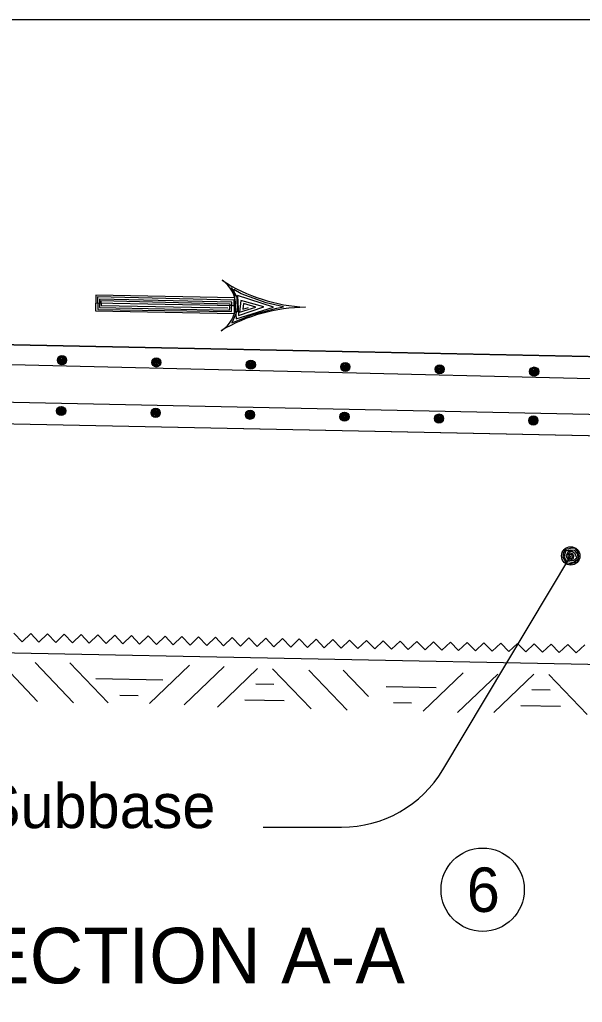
# Model space of a CAD drawing. Extents: x 10130 to 81668, y 5440 to 21644.
# Drawn here: x 17774.7 to 17977.5, y 9590.3 to 9944 of the extents above; entities that cross this region are included whole.
import ezdxf

# ---------------------------------------------------------------- set-up
doc = ezdxf.new("R2010")
doc.units = 0
for name, color, linetype in [('dsnStdBlockModified', 7, 'Continuous'), ('dsnStdBlockNotModified', 7, 'Continuous'), ('dsnStdBorder', 7, 'Continuous'), ('Level 2', 7, 'Continuous'), ('SheetBorder', 7, 'Continuous')]:
    doc.layers.add(name, color=color, linetype=linetype)

msp = doc.modelspace()

# ---------------------------------------------------------------- linework, layer by layer
at = {"layer": 'dsnStdBlockModified'}
msp.add_line((18198.1, 9797.36), (17466.58, 9812.52), dxfattribs=at)
at = {"layer": 'dsnStdBlockNotModified'}
for p, q in [((17852.17, 9844.06), (17852.17, 9844.06)), ((17852.26, 9841.03), (17802.12, 9842.03)), ((17852.11, 9838.2), (17852.11, 9838.2)), ((17927.27, 9674.05), (17973.29, 9751.03)), ((17862.47, 9653.35), (17890.76, 9653.35))]:
    msp.add_line(p, q, dxfattribs=at)
for points in [[(17850.94, 9847.58), (17853, 9844.16), (17853.16, 9839.21), (17851.25, 9834.92), (17858.71, 9837.84), (17867.4, 9840.18), (17869.85, 9840.69), (17863.61, 9842.07), (17854.6, 9845.38), (17851.93, 9846.88), (17852.72, 9836.34), (17866.15, 9840.58), (17853.2, 9844.78), (17853.56, 9837.51), (17862.77, 9840.71), (17854.42, 9842.94), (17853.96, 9838.76), (17859.83, 9840.51), (17855.4, 9841.86), (17855.11, 9839.86), (17857.25, 9840.44)], [(17852.22, 9843.87), (17802.18, 9844.87), (17802.06, 9839.2), (17852.11, 9838.2), (17852.04, 9843.05), (17802.81, 9844.23), (17802.85, 9839.72), (17851.02, 9838.94), (17851.21, 9842.32), (17803.49, 9843.46), (17803.55, 9840.45), (17850.4, 9839.51), (17850.57, 9841.64), (17804.04, 9842.83), (17804.07, 9841.13), (17849.79, 9840.28)], [(17973.03, 9747.99), (17974.15, 9748.49), (17975.88, 9749.03), (17976.22, 9750.79), (17975.98, 9752.34), (17974.87, 9753.77), (17973.22, 9753.62), (17971.47, 9753.37), (17970.64, 9751.99), (17970.49, 9750.52), (17971.52, 9748.61), (17972.79, 9748.45), (17974.53, 9748.89), (17975.95, 9750), (17975.9, 9751.65), (17974.79, 9752.98), (17973.23, 9753.13), (17971.49, 9752.79), (17971.23, 9751.81), (17970.88, 9750.63), (17971.69, 9749.19), (17972.96, 9749.23), (17974.41, 9749.47), (17975.46, 9750.28), (17974.93, 9751.72), (17973.83, 9752.57), (17972.37, 9752.62), (17972, 9751.83), (17971.54, 9750.94), (17972.26, 9749.8), (17973.34, 9749.54), (17974.3, 9750.05), (17974.37, 9751.12), (17973.86, 9751.88), (17972.87, 9752.15), (17972.4, 9751.75), (17972.12, 9751.15), (17972.64, 9750.29), (17973.32, 9750.12), (17973.99, 9750.53), (17973.88, 9751.11), (17973.38, 9751.48), (17972.7, 9751.47), (17972.71, 9750.98), (17973.3, 9750.7)]]:
    msp.add_lwpolyline(points, dxfattribs=at)
msp.add_circle((17973.29, 9751.02), 3.31, dxfattribs=at)
for centre, radius, start, end in [((17841.88, 9841.24), 10.67, 300.5647, 57.1354), ((17880.75, 9901.39), 60.95, 237.1358, 267.1658), ((17878.3, 9779.57), 60.95, 90.5343, 120.5643), ((17890.76, 9695.89), 42.54, 270, 329.1249)]:
    msp.add_arc(centre, radius, start, end, dxfattribs=at)
at = {"layer": 'dsnStdBorder'}
for p, q in [((18176.88, 9818.81), (17466.62, 9833.07)), ((17466.62, 9833.07), (18176.88, 9818.81)), ((17466.59, 9827.31), (18198.18, 9809.65)), ((17466.05, 9804.71), (18215.16, 9789.67)), ((17467.19, 9804.69), (18215.16, 9789.67)), ((17466.62, 9722.28), (18283.21, 9705.89)), ((17767.3, 9713.07), (17781.16, 9698.65)), ((17780.31, 9712.59), (17794.16, 9698.16)), ((17792.76, 9712.56), (17806.61, 9698.14)), ((17835.97, 9711.7), (17821.55, 9697.84)), ((17848.42, 9711.22), (17833.99, 9697.37)), ((17860.46, 9710.46), (17846.04, 9696.61)), ((17865.87, 9710.36), (17879.73, 9695.93)), ((17878.88, 9709.87), (17892.73, 9695.45)), ((17891.33, 9709.84), (17900.43, 9700.37)), ((17934.54, 9708.98), (17920.12, 9695.12)), ((17946.99, 9708.5), (17932.56, 9694.65)), ((17960, 9708.47), (17945.57, 9694.61)), ((17965.41, 9708.36), (17979.26, 9693.93))]:
    msp.add_line(p, q, dxfattribs=at)
for points in [[(17788.47, 9821.41), (17788.74, 9821.96), (17789.04, 9822.81), (17789.93, 9822.94), (17790.7, 9822.79), (17791.39, 9822.2), (17791.28, 9821.38), (17791.12, 9820.51), (17790.41, 9820.13), (17789.67, 9820.08), (17788.74, 9820.64), (17788.69, 9821.27), (17788.95, 9822.14), (17789.53, 9822.83), (17790.36, 9822.76), (17791, 9822.18), (17791.04, 9821.4), (17790.83, 9820.54), (17790.34, 9820.42), (17789.74, 9820.27), (17789.04, 9820.71), (17789.08, 9821.35), (17789.23, 9822.07), (17789.66, 9822.57), (17790.37, 9822.28), (17790.77, 9821.71), (17790.76, 9820.98), (17790.36, 9820.81), (17789.91, 9820.6), (17789.35, 9820.98), (17789.24, 9821.53), (17789.52, 9822), (17790.06, 9822.01), (17790.43, 9821.74), (17790.54, 9821.24), (17790.33, 9821.01), (17790.03, 9820.89), (17789.6, 9821.16), (17789.54, 9821.51), (17789.75, 9821.83), (17790.04, 9821.76), (17790.22, 9821.51), (17790.19, 9821.17), (17789.95, 9821.18), (17789.83, 9821.49)], [(17822.49, 9820.59), (17822.77, 9821.14), (17823.07, 9821.99), (17823.96, 9822.12), (17824.73, 9821.97), (17825.42, 9821.38), (17825.31, 9820.56), (17825.15, 9819.69), (17824.44, 9819.3), (17823.7, 9819.26), (17822.77, 9819.82), (17822.72, 9820.46), (17822.98, 9821.31), (17823.56, 9822.01), (17824.39, 9821.94), (17825.03, 9821.36), (17825.07, 9820.58), (17824.86, 9819.71), (17824.37, 9819.6), (17823.77, 9819.45), (17823.07, 9819.9), (17823.11, 9820.52), (17823.26, 9821.25), (17823.69, 9821.75), (17824.4, 9821.45), (17824.8, 9820.89), (17824.79, 9820.16), (17824.39, 9819.99), (17823.94, 9819.78), (17823.38, 9820.17), (17823.27, 9820.71), (17823.55, 9821.18), (17824.09, 9821.19), (17824.46, 9820.92), (17824.57, 9820.42), (17824.35, 9820.19), (17824.06, 9820.07), (17823.64, 9820.34), (17823.56, 9820.69), (17823.78, 9821.01), (17824.07, 9820.94), (17824.25, 9820.69), (17824.22, 9820.35), (17823.98, 9820.36), (17823.85, 9820.67)], [(17856.52, 9819.77), (17856.79, 9820.31), (17857.1, 9821.17), (17857.99, 9821.3), (17858.76, 9821.14), (17859.45, 9820.56), (17859.34, 9819.74), (17859.18, 9818.87), (17858.47, 9818.49), (17857.73, 9818.44), (17856.8, 9818.99), (17856.75, 9819.63), (17857, 9820.5), (17857.59, 9821.18), (17858.42, 9821.12), (17859.06, 9820.54), (17859.1, 9819.75), (17858.89, 9818.89), (17858.39, 9818.78), (17857.8, 9818.63), (17857.1, 9819.07), (17857.14, 9819.71), (17857.29, 9820.42), (17857.72, 9820.93), (17858.43, 9820.64), (17858.82, 9820.07), (17858.82, 9819.34), (17858.42, 9819.17), (17857.97, 9818.96), (17857.41, 9819.34), (17857.3, 9819.89), (17857.58, 9820.36), (17858.12, 9820.36), (17858.49, 9820.09), (17858.6, 9819.6), (17858.39, 9819.37), (17858.09, 9819.24), (17857.66, 9819.52), (17857.59, 9819.86), (17857.81, 9820.19), (17858.1, 9820.12), (17858.28, 9819.86), (17858.25, 9819.53), (17858.01, 9819.54), (17857.88, 9819.84)], [(17890.55, 9818.94), (17890.83, 9819.49), (17891.13, 9820.35), (17892.02, 9820.48), (17892.79, 9820.33), (17893.48, 9819.74), (17893.37, 9818.92), (17893.21, 9818.05), (17892.5, 9817.66), (17891.76, 9817.62), (17890.83, 9818.18), (17890.78, 9818.82), (17891.03, 9819.67), (17891.63, 9820.36), (17892.44, 9820.3), (17893.09, 9819.71), (17893.12, 9818.94), (17892.92, 9818.07), (17892.42, 9817.96), (17891.83, 9817.81), (17891.13, 9818.25), (17891.17, 9818.88), (17891.32, 9819.61), (17891.75, 9820.11), (17892.46, 9819.81), (17892.85, 9819.25), (17892.85, 9818.51), (17892.45, 9818.35), (17892, 9818.14), (17891.44, 9818.52), (17891.33, 9819.07), (17891.61, 9819.53), (17892.15, 9819.54), (17892.52, 9819.27), (17892.63, 9818.78), (17892.42, 9818.55), (17892.12, 9818.42), (17891.69, 9818.7), (17891.62, 9819.05), (17891.84, 9819.37), (17892.13, 9819.3), (17892.31, 9819.05), (17892.28, 9818.7), (17892.04, 9818.72), (17891.91, 9819.02)], [(17924.58, 9818.12), (17924.86, 9818.67), (17925.16, 9819.53), (17926.05, 9819.66), (17926.82, 9819.5), (17927.51, 9818.92), (17927.4, 9818.09), (17927.24, 9817.23), (17926.53, 9816.84), (17925.79, 9816.8), (17924.86, 9817.35), (17924.81, 9817.99), (17925.06, 9818.85), (17925.65, 9819.54), (17926.47, 9819.48), (17927.11, 9818.9), (17927.15, 9818.11), (17926.95, 9817.25), (17926.45, 9817.14), (17925.86, 9816.99), (17925.16, 9817.43), (17925.2, 9818.06), (17925.35, 9818.78), (17925.78, 9819.29), (17926.49, 9818.99), (17926.89, 9818.43), (17926.88, 9817.69), (17926.48, 9817.53), (17926.03, 9817.32), (17925.47, 9817.7), (17925.36, 9818.24), (17925.64, 9818.71), (17926.18, 9818.72), (17926.55, 9818.45), (17926.66, 9817.95), (17926.44, 9817.72), (17926.14, 9817.6), (17925.72, 9817.88), (17925.66, 9818.22), (17925.87, 9818.55), (17926.16, 9818.48), (17926.34, 9818.22), (17926.31, 9817.88), (17926.07, 9817.9), (17925.95, 9818.2)], [(17958.61, 9817.3), (17958.88, 9817.85), (17959.19, 9818.71), (17960.08, 9818.84), (17960.85, 9818.68), (17961.54, 9818.09), (17961.43, 9817.28), (17961.26, 9816.41), (17960.55, 9816.02), (17959.82, 9815.98), (17958.88, 9816.53), (17958.84, 9817.17), (17959.09, 9818.03), (17959.68, 9818.72), (17960.5, 9818.66), (17961.14, 9818.07), (17961.18, 9817.29), (17960.98, 9816.43), (17960.48, 9816.32), (17959.89, 9816.17), (17959.19, 9816.61), (17959.23, 9817.24), (17959.38, 9817.96), (17959.81, 9818.47), (17960.52, 9818.17), (17960.91, 9817.61), (17960.91, 9816.87), (17960.51, 9816.71), (17960.06, 9816.5), (17959.5, 9816.88), (17959.39, 9817.43), (17959.67, 9817.89), (17960.21, 9817.9), (17960.58, 9817.63), (17960.69, 9817.13), (17960.48, 9816.91), (17960.17, 9816.78), (17959.75, 9817.05), (17959.68, 9817.4), (17959.9, 9817.73), (17960.19, 9817.66), (17960.37, 9817.4), (17960.34, 9817.06), (17960.1, 9817.08), (17959.97, 9817.38)], [(17791.2, 9803.05), (17790.95, 9803.61), (17790.69, 9804.48), (17789.8, 9804.64), (17789.03, 9804.52), (17788.31, 9803.97), (17788.39, 9803.14), (17788.51, 9802.27), (17789.2, 9801.85), (17789.94, 9801.77), (17790.9, 9802.29), (17790.97, 9802.92), (17790.76, 9803.8), (17790.2, 9804.51), (17789.38, 9804.49), (17788.71, 9803.93), (17788.64, 9803.15), (17788.8, 9802.28), (17789.29, 9802.15), (17789.88, 9801.97), (17790.6, 9802.38), (17790.58, 9803.01), (17790.47, 9803.74), (17790.06, 9804.26), (17789.34, 9804), (17788.92, 9803.45), (17788.89, 9802.72), (17789.28, 9802.54), (17789.73, 9802.3), (17790.3, 9802.66), (17790.43, 9803.2), (17790.17, 9803.68), (17789.64, 9803.72), (17789.26, 9803.46), (17789.12, 9802.97), (17789.33, 9802.73), (17789.62, 9802.6), (17790.05, 9802.85), (17790.14, 9803.19), (17789.94, 9803.53), (17789.64, 9803.47), (17789.46, 9803.22), (17789.47, 9802.88), (17789.71, 9802.89), (17789.85, 9803.19)], [(17825.24, 9802.37), (17824.99, 9802.92), (17824.72, 9803.79), (17823.84, 9803.96), (17823.06, 9803.84), (17822.35, 9803.28), (17822.42, 9802.46), (17822.54, 9801.59), (17823.24, 9801.17), (17823.97, 9801.1), (17824.93, 9801.61), (17825.01, 9802.24), (17824.79, 9803.11), (17824.23, 9803.83), (17823.4, 9803.8), (17822.74, 9803.25), (17822.66, 9802.47), (17822.83, 9801.6), (17823.33, 9801.46), (17823.92, 9801.29), (17824.63, 9801.7), (17824.61, 9802.33), (17824.5, 9803.06), (17824.09, 9803.58), (17823.37, 9803.31), (17822.95, 9802.77), (17822.92, 9802.04), (17823.31, 9801.85), (17823.76, 9801.62), (17824.33, 9801.98), (17824.46, 9802.52), (17824.21, 9803), (17823.67, 9803.03), (17823.29, 9802.78), (17823.15, 9802.29), (17823.35, 9802.05), (17823.65, 9801.91), (17824.08, 9802.17), (17824.17, 9802.51), (17823.97, 9802.84), (17823.68, 9802.79), (17823.49, 9802.54), (17823.5, 9802.2), (17823.74, 9802.21), (17823.88, 9802.5)], [(17859.27, 9801.69), (17859.02, 9802.24), (17858.75, 9803.11), (17857.87, 9803.28), (17857.1, 9803.16), (17856.38, 9802.6), (17856.45, 9801.77), (17856.58, 9800.9), (17857.27, 9800.49), (17858, 9800.41), (17858.96, 9800.92), (17859.04, 9801.56), (17858.82, 9802.43), (17858.26, 9803.14), (17857.44, 9803.12), (17856.77, 9802.57), (17856.7, 9801.78), (17856.87, 9800.92), (17857.36, 9800.78), (17857.95, 9800.6), (17858.67, 9801.01), (17858.65, 9801.65), (17858.53, 9802.37), (17858.12, 9802.9), (17857.4, 9802.63), (17856.98, 9802.09), (17856.95, 9801.35), (17857.35, 9801.17), (17857.79, 9800.94), (17858.37, 9801.3), (17858.49, 9801.83), (17858.24, 9802.32), (17857.7, 9802.35), (17857.32, 9802.1), (17857.19, 9801.6), (17857.39, 9801.36), (17857.69, 9801.23), (17858.12, 9801.48), (17858.2, 9801.83), (17858, 9802.16), (17857.71, 9802.1), (17857.52, 9801.86), (17857.53, 9801.51), (17857.78, 9801.52), (17857.91, 9801.82)], [(17893.3, 9801), (17893.05, 9801.56), (17892.78, 9802.42), (17891.9, 9802.6), (17891.13, 9802.48), (17890.41, 9801.92), (17890.49, 9801.1), (17890.61, 9800.22), (17891.3, 9799.8), (17892.03, 9799.73), (17892.99, 9800.24), (17893.07, 9800.88), (17892.85, 9801.75), (17892.29, 9802.46), (17891.47, 9802.44), (17890.8, 9801.88), (17890.73, 9801.1), (17890.9, 9800.23), (17891.39, 9800.1), (17891.98, 9799.92), (17892.7, 9800.33), (17892.68, 9800.96), (17892.56, 9801.69), (17892.16, 9802.22), (17891.44, 9801.95), (17891.01, 9801.4), (17890.99, 9800.67), (17891.38, 9800.49), (17891.82, 9800.26), (17892.4, 9800.61), (17892.53, 9801.15), (17892.27, 9801.63), (17891.73, 9801.66), (17891.35, 9801.41), (17891.22, 9800.92), (17891.42, 9800.68), (17891.72, 9800.54), (17892.15, 9800.8), (17892.23, 9801.15), (17892.03, 9801.48), (17891.74, 9801.42), (17891.56, 9801.17), (17891.57, 9800.83), (17891.81, 9800.84), (17891.94, 9801.14)], [(17927.34, 9800.32), (17927.09, 9800.87), (17926.82, 9801.74), (17925.94, 9801.91), (17925.16, 9801.79), (17924.44, 9801.24), (17924.52, 9800.41), (17924.64, 9799.54), (17925.33, 9799.12), (17926.07, 9799.04), (17927.02, 9799.56), (17927.1, 9800.19), (17926.89, 9801.07), (17926.33, 9801.77), (17925.5, 9801.75), (17924.84, 9801.2), (17924.77, 9800.42), (17924.93, 9799.55), (17925.42, 9799.41), (17926.01, 9799.23), (17926.73, 9799.65), (17926.72, 9800.28), (17926.6, 9801.01), (17926.19, 9801.53), (17925.47, 9801.27), (17925.05, 9800.72), (17925.02, 9799.99), (17925.42, 9799.8), (17925.86, 9799.57), (17926.43, 9799.93), (17926.56, 9800.47), (17926.3, 9800.95), (17925.77, 9800.98), (17925.39, 9800.73), (17925.25, 9800.24), (17925.46, 9800), (17925.75, 9799.86), (17926.18, 9800.12), (17926.27, 9800.46), (17926.07, 9800.8), (17925.77, 9800.74), (17925.59, 9800.49), (17925.6, 9800.15), (17925.84, 9800.15), (17925.98, 9800.45)], [(17961.37, 9799.63), (17961.12, 9800.19), (17960.85, 9801.06), (17959.97, 9801.23), (17959.19, 9801.11), (17958.48, 9800.55), (17958.55, 9799.73), (17958.67, 9798.85), (17959.37, 9798.44), (17960.1, 9798.36), (17961.06, 9798.88), (17961.14, 9799.51), (17960.92, 9800.38), (17960.36, 9801.1), (17959.54, 9801.07), (17958.87, 9800.51), (17958.8, 9799.74), (17958.97, 9798.86), (17959.46, 9798.73), (17960.04, 9798.56), (17960.76, 9798.97), (17960.74, 9799.59), (17960.63, 9800.33), (17960.23, 9800.85), (17959.5, 9800.58), (17959.08, 9800.03), (17959.05, 9799.3), (17959.44, 9799.12), (17959.89, 9798.89), (17960.46, 9799.25), (17960.59, 9799.79), (17960.34, 9800.27), (17959.8, 9800.3), (17959.42, 9800.05), (17959.28, 9799.56), (17959.49, 9799.32), (17959.78, 9799.18), (17960.22, 9799.44), (17960.3, 9799.78), (17960.1, 9800.11), (17959.81, 9800.06), (17959.62, 9799.81), (17959.63, 9799.47), (17959.87, 9799.47), (17960.01, 9799.77)], [(17772.68, 9723.17), (17775.65, 9720.08), (17778.73, 9723.05), (17781.69, 9719.96), (17784.78, 9722.93), (17787.74, 9719.85), (17790.83, 9722.81), (17793.79, 9719.72), (17796.87, 9722.68), (17799.84, 9719.6), (17802.93, 9722.57), (17805.89, 9719.48), (17808.98, 9722.45), (17810.45, 9720.9)], [(17810.45, 9720.9), (17811.94, 9719.36), (17815.02, 9722.32), (17817.98, 9719.24), (17821.07, 9722.2), (17824.04, 9719.11), (17827.12, 9722.08), (17830.09, 9718.99), (17833.17, 9721.96), (17836.13, 9718.87), (17839.22, 9721.84), (17842.18, 9718.75), (17845.26, 9721.71), (17848.23, 9718.63), (17851.31, 9721.59), (17854.28, 9718.51), (17857.36, 9721.47), (17860.33, 9718.39), (17863.41, 9721.35), (17866.37, 9718.27), (17869.46, 9721.23), (17872.42, 9718.14), (17875.51, 9721.11), (17878.47, 9718.02), (17881.56, 9720.99), (17883.04, 9719.44)], [(17883.04, 9719.44), (17884.52, 9717.9), (17887.61, 9720.87), (17890.57, 9717.78), (17893.65, 9720.74), (17896.62, 9717.66), (17899.7, 9720.62), (17902.67, 9717.54), (17905.75, 9720.5), (17908.72, 9717.42), (17911.8, 9720.38), (17914.76, 9717.29), (17917.85, 9720.26), (17920.81, 9717.17), (17923.9, 9720.14), (17926.86, 9717.05), (17929.95, 9720.02), (17932.91, 9716.93), (17936, 9719.89), (17938.96, 9716.81), (17942.04, 9719.77), (17945.01, 9716.69), (17948.09, 9719.65), (17951.06, 9716.57), (17954.14, 9719.53), (17955.62, 9717.99)], [(17955.62, 9717.99), (17957.11, 9716.45), (17960.19, 9719.41), (17963.16, 9716.32), (17966.24, 9719.29), (17969.2, 9716.2), (17972.29, 9719.17), (17975.25, 9716.08), (17978.34, 9719.05)], [(17802.23, 9706.9), (17826.28, 9706.41)], [(17859.79, 9704.98), (17866.33, 9704.85)], [(17906.79, 9704.06), (17924.85, 9703.7)], [(17959.33, 9702.98), (17965.86, 9702.85)], [(17810.87, 9700.92), (17817.4, 9700.79)], [(17855.85, 9699.2), (17870.04, 9698.92)], [(17909.44, 9698.2), (17915.97, 9698.07)], [(17955.38, 9697.2), (17969.57, 9696.92)]]:
    msp.add_lwpolyline(points, dxfattribs=at)
for centre in [(17789.99, 9821.47), (17824.02, 9820.65), (17858.05, 9819.83), (17892.08, 9819.01), (17926.11, 9818.18), (17960.13, 9817.36), (17789.69, 9803.17), (17823.72, 9802.49), (17857.75, 9801.81), (17891.78, 9801.12), (17925.82, 9800.44), (17959.85, 9799.76)]:
    msp.add_circle(centre, 1.65, dxfattribs=at)
at = {"layer": 'Level 2'}
msp.add_circle((17941.58, 9630.86), 15, dxfattribs=at)
at = {"layer": 'SheetBorder'}
msp.add_lwpolyline([(17332.52, 9944.02), (20467.53, 9944.02), (20467.53, 7924.02), (17332.52, 7924.02)], close=True, dxfattribs=at)

# ---------------------------------------------------------------- texts
at = {"layer": 'dsnStdBlockNotModified'}
for s, height, p in [('Modified Subbase', 16, (17673.98, 9653.04)), ('SECTION A-A', 20, (17742.67, 9597.15))]:
    msp.add_text(s, height=height, dxfattribs=at).set_placement(p)
at = {"layer": 'Level 2'}
msp.add_text('6', height=16, dxfattribs=at).set_placement((17935.87, 9622.86))

doc.saveas('drawing.dxf')
